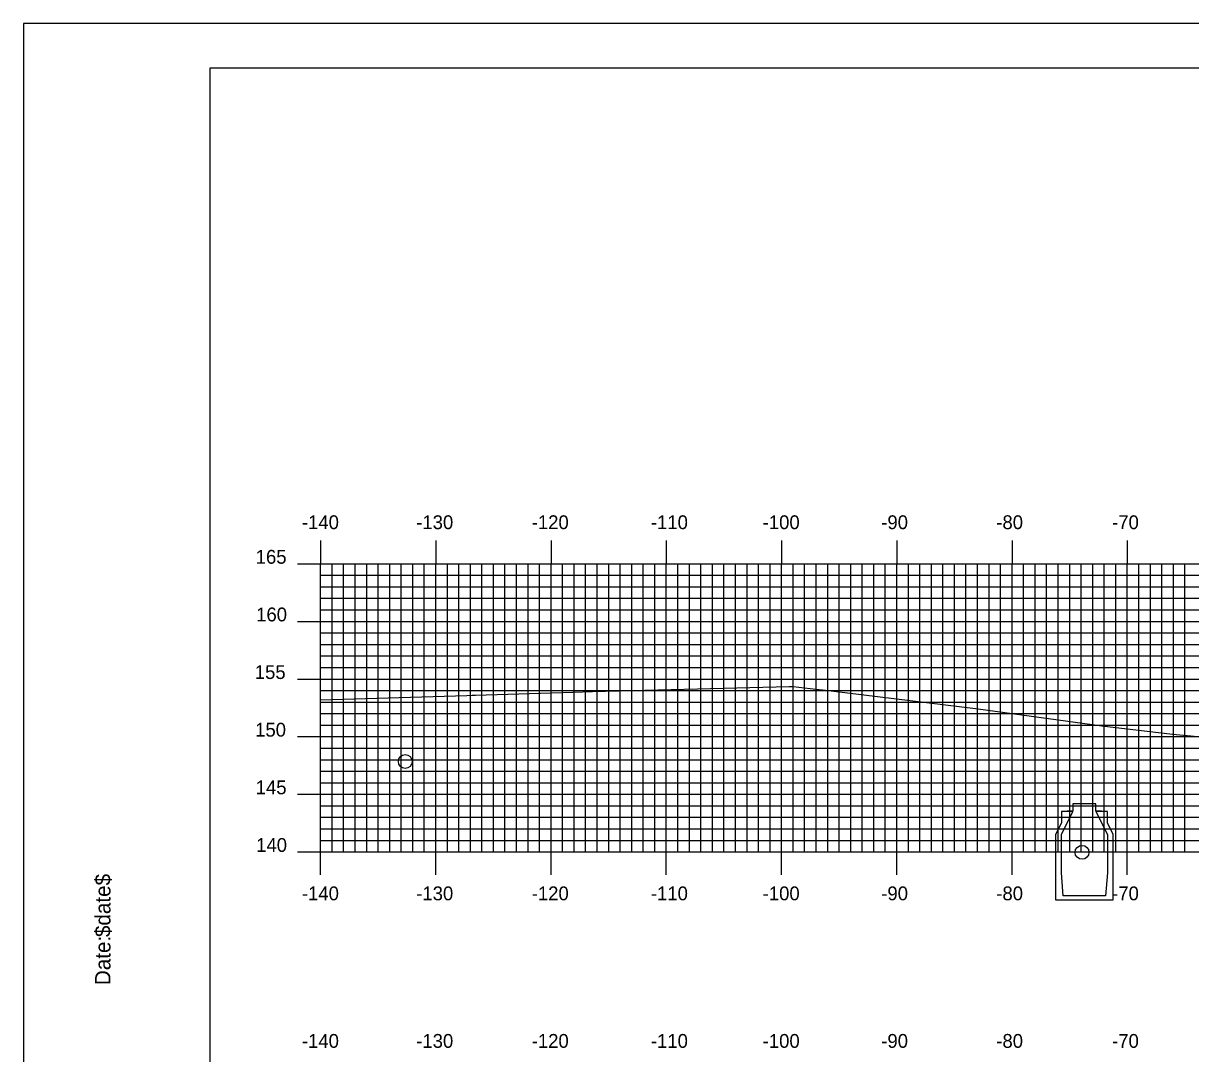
# Model space of a CAD drawing. Extents: x 861045 to 861388, y 364765 to 364985.
# Drawn here: x 861045.1 to 861146.4, y 364895.8 to 364985.2 of the extents above; entities that cross this region are included whole.
import ezdxf

# ---------------------------------------------------------------- set-up
doc = ezdxf.new("R2010")
doc.units = 0
for name, color, linetype in [('BORDER', 7, 'Continuous'), ('H_V ANNOTATION', 7, 'Continuous'), ('MAJOR', 7, 'Continuous'), ('MINOR', 7, 'Continuous'), ('PLOT BOUNDARY', 7, 'Continuous'), ('S_Drainage_CB', 7, 'Continuous'), ('S_Drainage_Invert', 7, 'Continuous'), ('S_Roadway_Centerline', 7, 'Continuous')]:
    doc.layers.add(name, color=color, linetype=linetype)

msp = doc.modelspace()

# ---------------------------------------------------------------- linework, layer by layer
at = {"layer": 'BORDER'}
msp.add_lwpolyline([(861061.33, 364771.3), (861381.33, 364771.3), (861381.33, 364981.3), (861061.33, 364981.3)], close=True, dxfattribs=at)
at = {"layer": 'MAJOR'}
for p, q in [((861070.93, 364940.31), (861070.93, 364938.3)), ((861080.93, 364940.31), (861080.93, 364938.3)), ((861090.93, 364940.31), (861090.93, 364938.3)), ((861100.93, 364940.31), (861100.93, 364938.3)), ((861110.93, 364940.31), (861110.93, 364938.3)), ((861120.93, 364940.31), (861120.93, 364938.3)), ((861130.93, 364940.31), (861130.93, 364938.3)), ((861140.93, 364940.31), (861140.93, 364938.3)), ((861068.92, 364938.3), (861070.93, 364938.3)), ((861070.93, 364938.3), (861350.93, 364938.3)), ((861070.93, 364913.3), (861070.93, 364938.3)), ((861070.93, 364938.3), (861350.93, 364938.3)), ((861070.93, 364913.3), (861070.93, 364938.3)), ((861070.93, 364913.3), (861070.93, 364938.3)), ((861070.93, 364938.3), (861350.93, 364938.3)), ((861080.93, 364913.3), (861080.93, 364938.3)), ((861080.93, 364913.3), (861080.93, 364938.3)), ((861090.93, 364913.3), (861090.93, 364938.3)), ((861090.93, 364913.3), (861090.93, 364938.3)), ((861100.93, 364913.3), (861100.93, 364938.3)), ((861100.93, 364913.3), (861100.93, 364938.3)), ((861110.93, 364913.3), (861110.93, 364938.3)), ((861110.93, 364913.3), (861110.93, 364938.3)), ((861120.93, 364913.3), (861120.93, 364938.3)), ((861120.93, 364913.3), (861120.93, 364938.3)), ((861130.93, 364913.3), (861130.93, 364938.3)), ((861130.93, 364913.3), (861130.93, 364938.3)), ((861140.93, 364913.3), (861140.93, 364938.3)), ((861140.93, 364913.3), (861140.93, 364938.3)), ((861068.92, 364933.3), (861070.93, 364933.3)), ((861070.93, 364933.3), (861350.93, 364933.3)), ((861070.93, 364933.3), (861350.93, 364933.3)), ((861068.92, 364928.3), (861070.93, 364928.3)), ((861070.93, 364928.3), (861350.93, 364928.3)), ((861070.93, 364928.3), (861350.93, 364928.3)), ((861068.92, 364923.3), (861070.93, 364923.3)), ((861070.93, 364923.3), (861350.93, 364923.3)), ((861070.93, 364923.3), (861350.93, 364923.3)), ((861068.92, 364918.3), (861070.93, 364918.3)), ((861070.93, 364918.3), (861350.93, 364918.3)), ((861070.93, 364918.3), (861350.93, 364918.3)), ((861068.92, 364913.3), (861070.93, 364913.3)), ((861070.93, 364913.3), (861350.93, 364913.3)), ((861070.93, 364913.3), (861350.93, 364913.3)), ((861070.93, 364913.3), (861350.93, 364913.3)), ((861070.93, 364911.3), (861070.93, 364913.3)), ((861080.93, 364911.3), (861080.93, 364913.3)), ((861090.93, 364911.3), (861090.93, 364913.3)), ((861100.93, 364911.3), (861100.93, 364913.3)), ((861110.93, 364911.3), (861110.93, 364913.3)), ((861120.93, 364911.3), (861120.93, 364913.3)), ((861130.93, 364911.3), (861130.93, 364913.3)), ((861140.93, 364911.3), (861140.93, 364913.3))]:
    msp.add_line(p, q, dxfattribs=at)
at = {"layer": 'MINOR'}
for p, q in [((861071.93, 364913.3), (861071.93, 364938.3)), ((861071.93, 364913.3), (861071.93, 364938.3)), ((861072.93, 364913.3), (861072.93, 364938.3)), ((861072.93, 364913.3), (861072.93, 364938.3)), ((861073.93, 364913.3), (861073.93, 364938.3)), ((861073.93, 364913.3), (861073.93, 364938.3)), ((861074.93, 364913.3), (861074.93, 364938.3)), ((861074.93, 364913.3), (861074.93, 364938.3)), ((861075.93, 364913.3), (861075.93, 364938.3)), ((861075.93, 364913.3), (861075.93, 364938.3)), ((861076.93, 364913.3), (861076.93, 364938.3)), ((861076.93, 364913.3), (861076.93, 364938.3)), ((861077.93, 364913.3), (861077.93, 364938.3)), ((861077.93, 364913.3), (861077.93, 364938.3)), ((861078.93, 364913.3), (861078.93, 364938.3)), ((861078.93, 364913.3), (861078.93, 364938.3)), ((861079.93, 364913.3), (861079.93, 364938.3)), ((861079.93, 364913.3), (861079.93, 364938.3)), ((861081.93, 364913.3), (861081.93, 364938.3)), ((861081.93, 364913.3), (861081.93, 364938.3)), ((861082.93, 364913.3), (861082.93, 364938.3)), ((861082.93, 364913.3), (861082.93, 364938.3)), ((861083.93, 364913.3), (861083.93, 364938.3)), ((861083.93, 364913.3), (861083.93, 364938.3)), ((861084.93, 364913.3), (861084.93, 364938.3)), ((861084.93, 364913.3), (861084.93, 364938.3)), ((861085.93, 364913.3), (861085.93, 364938.3)), ((861085.93, 364913.3), (861085.93, 364938.3)), ((861086.93, 364913.3), (861086.93, 364938.3)), ((861086.93, 364913.3), (861086.93, 364938.3)), ((861087.93, 364913.3), (861087.93, 364938.3)), ((861087.93, 364913.3), (861087.93, 364938.3)), ((861088.93, 364913.3), (861088.93, 364938.3)), ((861088.93, 364913.3), (861088.93, 364938.3)), ((861089.93, 364913.3), (861089.93, 364938.3)), ((861089.93, 364913.3), (861089.93, 364938.3)), ((861091.93, 364913.3), (861091.93, 364938.3)), ((861091.93, 364913.3), (861091.93, 364938.3)), ((861092.93, 364913.3), (861092.93, 364938.3)), ((861092.93, 364913.3), (861092.93, 364938.3)), ((861093.93, 364913.3), (861093.93, 364938.3)), ((861093.93, 364913.3), (861093.93, 364938.3)), ((861094.93, 364913.3), (861094.93, 364938.3)), ((861094.93, 364913.3), (861094.93, 364938.3)), ((861095.93, 364913.3), (861095.93, 364938.3)), ((861095.93, 364913.3), (861095.93, 364938.3)), ((861096.93, 364913.3), (861096.93, 364938.3)), ((861096.93, 364913.3), (861096.93, 364938.3)), ((861097.93, 364913.3), (861097.93, 364938.3)), ((861097.93, 364913.3), (861097.93, 364938.3)), ((861098.93, 364913.3), (861098.93, 364938.3)), ((861098.93, 364913.3), (861098.93, 364938.3)), ((861099.93, 364913.3), (861099.93, 364938.3)), ((861099.93, 364913.3), (861099.93, 364938.3)), ((861101.93, 364913.3), (861101.93, 364938.3)), ((861101.93, 364913.3), (861101.93, 364938.3)), ((861102.93, 364913.3), (861102.93, 364938.3)), ((861102.93, 364913.3), (861102.93, 364938.3)), ((861103.93, 364913.3), (861103.93, 364938.3)), ((861103.93, 364913.3), (861103.93, 364938.3)), ((861104.93, 364913.3), (861104.93, 364938.3)), ((861104.93, 364913.3), (861104.93, 364938.3)), ((861105.93, 364913.3), (861105.93, 364938.3)), ((861105.93, 364913.3), (861105.93, 364938.3)), ((861106.93, 364913.3), (861106.93, 364938.3)), ((861106.93, 364913.3), (861106.93, 364938.3)), ((861107.93, 364913.3), (861107.93, 364938.3)), ((861107.93, 364913.3), (861107.93, 364938.3)), ((861108.93, 364913.3), (861108.93, 364938.3)), ((861108.93, 364913.3), (861108.93, 364938.3)), ((861109.93, 364913.3), (861109.93, 364938.3)), ((861109.93, 364913.3), (861109.93, 364938.3)), ((861111.93, 364913.3), (861111.93, 364938.3)), ((861111.93, 364913.3), (861111.93, 364938.3)), ((861112.93, 364913.3), (861112.93, 364938.3)), ((861112.93, 364913.3), (861112.93, 364938.3)), ((861113.93, 364913.3), (861113.93, 364938.3)), ((861113.93, 364913.3), (861113.93, 364938.3)), ((861114.93, 364913.3), (861114.93, 364938.3)), ((861114.93, 364913.3), (861114.93, 364938.3)), ((861115.93, 364913.3), (861115.93, 364938.3)), ((861115.93, 364913.3), (861115.93, 364938.3)), ((861116.93, 364913.3), (861116.93, 364938.3)), ((861116.93, 364913.3), (861116.93, 364938.3)), ((861117.93, 364913.3), (861117.93, 364938.3)), ((861117.93, 364913.3), (861117.93, 364938.3)), ((861118.93, 364913.3), (861118.93, 364938.3)), ((861118.93, 364913.3), (861118.93, 364938.3)), ((861119.93, 364913.3), (861119.93, 364938.3)), ((861119.93, 364913.3), (861119.93, 364938.3)), ((861121.93, 364913.3), (861121.93, 364938.3)), ((861121.93, 364913.3), (861121.93, 364938.3)), ((861122.93, 364913.3), (861122.93, 364938.3)), ((861122.93, 364913.3), (861122.93, 364938.3)), ((861123.93, 364913.3), (861123.93, 364938.3)), ((861123.93, 364913.3), (861123.93, 364938.3)), ((861124.93, 364913.3), (861124.93, 364938.3)), ((861124.93, 364913.3), (861124.93, 364938.3)), ((861125.93, 364913.3), (861125.93, 364938.3)), ((861125.93, 364913.3), (861125.93, 364938.3)), ((861126.93, 364913.3), (861126.93, 364938.3)), ((861126.93, 364913.3), (861126.93, 364938.3)), ((861127.93, 364913.3), (861127.93, 364938.3)), ((861127.93, 364913.3), (861127.93, 364938.3)), ((861128.93, 364913.3), (861128.93, 364938.3)), ((861128.93, 364913.3), (861128.93, 364938.3)), ((861129.93, 364913.3), (861129.93, 364938.3)), ((861129.93, 364913.3), (861129.93, 364938.3)), ((861131.93, 364913.3), (861131.93, 364938.3)), ((861131.93, 364913.3), (861131.93, 364938.3)), ((861132.93, 364913.3), (861132.93, 364938.3)), ((861132.93, 364913.3), (861132.93, 364938.3)), ((861133.93, 364913.3), (861133.93, 364938.3)), ((861133.93, 364913.3), (861133.93, 364938.3)), ((861134.93, 364913.3), (861134.93, 364938.3)), ((861134.93, 364913.3), (861134.93, 364938.3)), ((861135.93, 364913.3), (861135.93, 364938.3)), ((861135.93, 364913.3), (861135.93, 364938.3)), ((861136.93, 364913.3), (861136.93, 364938.3)), ((861136.93, 364913.3), (861136.93, 364938.3)), ((861137.93, 364913.3), (861137.93, 364938.3)), ((861137.93, 364913.3), (861137.93, 364938.3)), ((861138.93, 364913.3), (861138.93, 364938.3)), ((861138.93, 364913.3), (861138.93, 364938.3)), ((861139.93, 364913.3), (861139.93, 364938.3)), ((861139.93, 364913.3), (861139.93, 364938.3)), ((861141.93, 364913.3), (861141.93, 364938.3)), ((861141.93, 364913.3), (861141.93, 364938.3)), ((861142.93, 364913.3), (861142.93, 364938.3)), ((861142.93, 364913.3), (861142.93, 364938.3)), ((861143.93, 364913.3), (861143.93, 364938.3)), ((861143.93, 364913.3), (861143.93, 364938.3)), ((861144.93, 364913.3), (861144.93, 364938.3)), ((861144.93, 364913.3), (861144.93, 364938.3)), ((861145.93, 364913.3), (861145.93, 364938.3)), ((861145.93, 364913.3), (861145.93, 364938.3)), ((861070.93, 364937.3), (861350.93, 364937.3)), ((861070.93, 364937.3), (861350.93, 364937.3)), ((861070.93, 364937.3), (861072.93, 364937.3)), ((861070.93, 364936.3), (861350.93, 364936.3)), ((861070.93, 364936.3), (861350.93, 364936.3)), ((861070.93, 364936.3), (861072.93, 364936.3)), ((861070.93, 364935.3), (861350.93, 364935.3)), ((861070.93, 364935.3), (861350.93, 364935.3)), ((861070.93, 364935.3), (861072.93, 364935.3)), ((861070.93, 364934.3), (861350.93, 364934.3)), ((861070.93, 364934.3), (861350.93, 364934.3)), ((861070.93, 364934.3), (861072.93, 364934.3)), ((861070.93, 364932.3), (861350.93, 364932.3)), ((861070.93, 364932.3), (861350.93, 364932.3)), ((861070.93, 364932.3), (861072.93, 364932.3)), ((861070.93, 364931.3), (861350.93, 364931.3)), ((861070.93, 364931.3), (861350.93, 364931.3)), ((861070.93, 364931.3), (861072.93, 364931.3)), ((861070.93, 364930.3), (861350.93, 364930.3)), ((861070.93, 364930.3), (861350.93, 364930.3)), ((861070.93, 364930.3), (861072.93, 364930.3)), ((861070.93, 364929.3), (861350.93, 364929.3)), ((861070.93, 364929.3), (861350.93, 364929.3)), ((861070.93, 364929.3), (861072.93, 364929.3)), ((861070.93, 364927.3), (861350.93, 364927.3)), ((861070.93, 364927.3), (861350.93, 364927.3)), ((861070.93, 364927.3), (861072.93, 364927.3)), ((861070.93, 364926.3), (861350.93, 364926.3)), ((861070.93, 364926.3), (861350.93, 364926.3)), ((861070.93, 364926.3), (861072.93, 364926.3)), ((861070.93, 364925.3), (861350.93, 364925.3)), ((861070.93, 364925.3), (861350.93, 364925.3)), ((861070.93, 364925.3), (861072.93, 364925.3)), ((861070.93, 364924.3), (861350.93, 364924.3)), ((861070.93, 364924.3), (861350.93, 364924.3)), ((861070.93, 364924.3), (861072.93, 364924.3)), ((861070.93, 364922.3), (861350.93, 364922.3)), ((861070.93, 364922.3), (861350.93, 364922.3)), ((861070.93, 364922.3), (861072.93, 364922.3)), ((861070.93, 364921.3), (861350.93, 364921.3)), ((861070.93, 364921.3), (861350.93, 364921.3)), ((861070.93, 364921.3), (861072.93, 364921.3)), ((861070.93, 364920.3), (861350.93, 364920.3)), ((861070.93, 364920.3), (861350.93, 364920.3)), ((861070.93, 364920.3), (861072.93, 364920.3)), ((861070.93, 364919.3), (861350.93, 364919.3)), ((861070.93, 364919.3), (861350.93, 364919.3)), ((861070.93, 364919.3), (861072.93, 364919.3)), ((861070.93, 364917.3), (861350.93, 364917.3)), ((861070.93, 364917.3), (861350.93, 364917.3)), ((861070.93, 364917.3), (861072.93, 364917.3)), ((861070.93, 364916.3), (861350.93, 364916.3)), ((861070.93, 364916.3), (861350.93, 364916.3)), ((861070.93, 364916.3), (861072.93, 364916.3)), ((861070.93, 364915.3), (861350.93, 364915.3)), ((861070.93, 364915.3), (861350.93, 364915.3)), ((861070.93, 364915.3), (861072.93, 364915.3)), ((861070.93, 364914.3), (861350.93, 364914.3)), ((861070.93, 364914.3), (861350.93, 364914.3)), ((861070.93, 364914.3), (861072.93, 364914.3))]:
    msp.add_line(p, q, dxfattribs=at)
at = {"layer": 'PLOT BOUNDARY'}
msp.add_lwpolyline([(861045.14, 364765.18), (861385.14, 364765.18), (861385.14, 364985.18), (861045.14, 364985.18)], close=True, dxfattribs=at)
at = {"layer": 'S_Drainage_CB'}
for p, q in [((861136.19, 364916.8), (861135.21, 364916.8)), ((861135.21, 364916.8), (861135.21, 364915.81)), ((861135.21, 364914.8), (861136.19, 364916.8)), ((861139.21, 364916.8), (861138.19, 364916.8)), ((861138.19, 364916.8), (861139.21, 364914.8)), ((861139.21, 364915.81), (861139.21, 364916.8)), ((861135.21, 364915.81), (861134.71, 364914.8)), ((861139.7, 364914.8), (861139.21, 364915.81)), ((861134.71, 364914.8), (861134.71, 364909.15)), ((861135.21, 364911.48), (861135.21, 364914.8)), ((861139.21, 364914.8), (861139.21, 364911.48)), ((861139.7, 364909.15), (861139.7, 364914.8)), ((861135.37, 364909.48), (861135.21, 364911.48)), ((861139.21, 364911.48), (861139.04, 364909.48)), ((861134.71, 364909.15), (861139.7, 364909.15)), ((861139.04, 364909.48), (861135.37, 364909.48))]:
    msp.add_line(p, q, dxfattribs=at)
msp.add_lwpolyline([(861138.68, 364916.84), (861138.19, 364916.84), (861138.19, 364917.46), (861136.19, 364917.46), (861136.19, 364916.84), (861135.7, 364916.84)], dxfattribs=at)
at = {"layer": 'S_Drainage_Invert'}
for centre in [(861078.28, 364921.14), (861137, 364913.26)]:
    msp.add_circle(centre, 0.6, dxfattribs=at)
at = {"layer": 'S_Roadway_Centerline'}
msp.add_lwpolyline([(861070.93, 364926.49), (861083.61, 364926.88), (861084.09, 364926.9), (861084.38, 364926.9), (861092.83, 364927.17), (861094.53, 364927.22), (861111.6, 364927.65), (861111.95, 364927.65), (861113.42, 364927.49), (861115, 364927.29), (861127.99, 364925.72), (861138.72, 364924.25), (861144.84, 364923.5), (861148.64, 364923.16)], dxfattribs=at)

# ---------------------------------------------------------------- texts
at = {"layer": 'BORDER'}
for s, p in [('$date$', (861052.7, 364905.91)), ('Date:', (861052.7, 364901.74))]:
    msp.add_text(s, height=1.339, rotation=90, dxfattribs=at).set_placement(p)
at = {"layer": 'H_V ANNOTATION'}
for s, p in [('-140', (861069.31, 364941.3)), ('-130', (861079.23, 364941.3)), ('-120', (861089.25, 364941.3)), ('-110', (861099.59, 364941.3)), ('-100', (861109.29, 364941.3)), ('-90', (861119.58, 364941.3)), ('-80', (861129.56, 364941.3)), ('-70', (861139.61, 364941.3)), ('165', (861065.3, 364938.3)), ('160', (861065.34, 364933.3)), ('155', (861065.22, 364928.3)), ('150', (861065.25, 364923.3)), ('145', (861065.3, 364918.3)), ('140', (861065.34, 364913.3)), ('-140', (861069.31, 364909.1)), ('-130', (861079.23, 364909.1)), ('-120', (861089.25, 364909.1)), ('-110', (861099.59, 364909.1)), ('-100', (861109.29, 364909.1)), ('-90', (861119.58, 364909.1)), ('-80', (861129.56, 364909.1)), ('-70', (861139.61, 364909.1)), ('-140', (861069.31, 364896.3)), ('-130', (861079.23, 364896.3)), ('-120', (861089.25, 364896.3)), ('-110', (861099.59, 364896.3)), ('-100', (861109.29, 364896.3)), ('-90', (861119.58, 364896.3)), ('-80', (861129.56, 364896.3)), ('-70', (861139.61, 364896.3))]:
    msp.add_text(s, height=1.2, dxfattribs=at).set_placement(p)
at = {"layer": 'MAJOR'}
msp.add_text('-', height=0.012, dxfattribs=at).set_placement((861070.92, 364913.3))

doc.saveas('drawing.dxf')
